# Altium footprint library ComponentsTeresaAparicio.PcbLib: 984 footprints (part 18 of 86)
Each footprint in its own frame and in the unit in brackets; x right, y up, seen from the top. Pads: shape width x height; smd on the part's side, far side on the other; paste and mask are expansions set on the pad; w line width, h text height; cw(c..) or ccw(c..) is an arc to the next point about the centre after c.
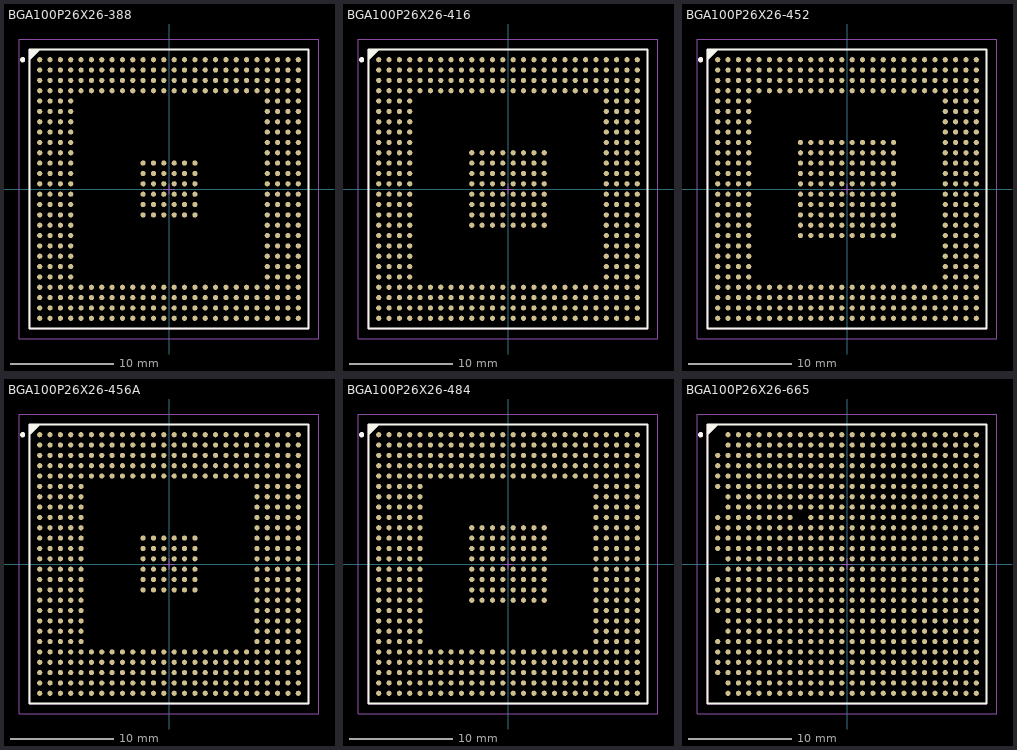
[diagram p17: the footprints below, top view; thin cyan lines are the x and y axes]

## BGA100P26X26-388 [mm] "BGA, 388-Leads, Body 27x27mm, Pitch 1mm"
height 2.55
pads (388):
  round 0.5 smd: A1(-12.5,12.5) A2(-11.5,12.5) A3(-10.5,12.5) A4(-9.5,12.5) A5(-8.5,12.5) A6(-7.5,12.5) A7(-6.5,12.5) A8(-5.5,12.5) A9(-4.5,12.5) A10(-3.5,12.5) A11(-2.5,12.5) A12(-1.5,12.5) A13(-0.5,12.5) A14(0.5,12.5) A15(1.5,12.5) A16(2.5,12.5) A17(3.5,12.5) A18(4.5,12.5) A19(5.5,12.5) A20(6.5,12.5) A21(7.5,12.5) A22(8.5,12.5) A23(9.5,12.5) A24(10.5,12.5) A25(11.5,12.5) A26(12.5,12.5) AA1(-12.5,-7.5) AA2(-11.5,-7.5) AA3(-10.5,-7.5) AA4(-9.5,-7.5) AA23(9.5,-7.5) AA24(10.5,-7.5) AA25(11.5,-7.5) AA26(12.5,-7.5) AB1(-12.5,-8.5) AB2(-11.5,-8.5) AB3(-10.5,-8.5) AB4(-9.5,-8.5) AB23(9.5,-8.5) AB24(10.5,-8.5) AB25(11.5,-8.5) AB26(12.5,-8.5) AC1(-12.5,-9.5) AC2(-11.5,-9.5) AC3(-10.5,-9.5) AC4(-9.5,-9.5) AC5(-8.5,-9.5) AC6(-7.5,-9.5) AC7(-6.5,-9.5) AC8(-5.5,-9.5) AC9(-4.5,-9.5) AC10(-3.5,-9.5) AC11(-2.5,-9.5) AC12(-1.5,-9.5) AC13(-0.5,-9.5) AC14(0.5,-9.5) AC15(1.5,-9.5) AC16(2.5,-9.5) AC17(3.5,-9.5) AC18(4.5,-9.5) AC19(5.5,-9.5) AC20(6.5,-9.5) AC21(7.5,-9.5) AC22(8.5,-9.5) AC23(9.5,-9.5) AC24(10.5,-9.5) AC25(11.5,-9.5) AC26(12.5,-9.5) AD1(-12.5,-10.5) AD2(-11.5,-10.5) AD3(-10.5,-10.5) AD4(-9.5,-10.5) AD5(-8.5,-10.5) AD6(-7.5,-10.5) AD7(-6.5,-10.5) AD8(-5.5,-10.5) AD9(-4.5,-10.5) AD10(-3.5,-10.5) AD11(-2.5,-10.5) AD12(-1.5,-10.5) AD13(-0.5,-10.5) AD14(0.5,-10.5) AD15(1.5,-10.5) AD16(2.5,-10.5) AD17(3.5,-10.5) AD18(4.5,-10.5) AD19(5.5,-10.5) AD20(6.5,-10.5) AD21(7.5,-10.5) AD22(8.5,-10.5) AD23(9.5,-10.5) AD24(10.5,-10.5) AD25(11.5,-10.5) AD26(12.5,-10.5) AE1(-12.5,-11.5) AE2(-11.5,-11.5) AE3(-10.5,-11.5) AE4(-9.5,-11.5) AE5(-8.5,-11.5) AE6(-7.5,-11.5) AE7(-6.5,-11.5) AE8(-5.5,-11.5) AE9(-4.5,-11.5) AE10(-3.5,-11.5) AE11(-2.5,-11.5) AE12(-1.5,-11.5) AE13(-0.5,-11.5) AE14(0.5,-11.5) AE15(1.5,-11.5) AE16(2.5,-11.5) AE17(3.5,-11.5) AE18(4.5,-11.5) AE19(5.5,-11.5) AE20(6.5,-11.5) AE21(7.5,-11.5) AE22(8.5,-11.5) AE23(9.5,-11.5) AE24(10.5,-11.5) AE25(11.5,-11.5) AE26(12.5,-11.5) AF1(-12.5,-12.5) AF2(-11.5,-12.5) AF3(-10.5,-12.5) AF4(-9.5,-12.5) AF5(-8.5,-12.5) AF6(-7.5,-12.5) AF7(-6.5,-12.5) AF8(-5.5,-12.5) AF9(-4.5,-12.5) AF10(-3.5,-12.5) AF11(-2.5,-12.5) AF12(-1.5,-12.5) AF13(-0.5,-12.5) AF14(0.5,-12.5) AF15(1.5,-12.5) AF16(2.5,-12.5) AF17(3.5,-12.5) AF18(4.5,-12.5) AF19(5.5,-12.5) AF20(6.5,-12.5) AF21(7.5,-12.5) AF22(8.5,-12.5) AF23(9.5,-12.5) AF24(10.5,-12.5) AF25(11.5,-12.5) AF26(12.5,-12.5) B1(-12.5,11.5) B2(-11.5,11.5) B3(-10.5,11.5) B4(-9.5,11.5) B5(-8.5,11.5) B6(-7.5,11.5) B7(-6.5,11.5) B8(-5.5,11.5) B9(-4.5,11.5) B10(-3.5,11.5) B11(-2.5,11.5) B12(-1.5,11.5) B13(-0.5,11.5) B14(0.5,11.5) B15(1.5,11.5) B16(2.5,11.5) B17(3.5,11.5) B18(4.5,11.5) B19(5.5,11.5) B20(6.5,11.5) B21(7.5,11.5) B22(8.5,11.5) B23(9.5,11.5) B24(10.5,11.5) B25(11.5,11.5) B26(12.5,11.5) C1(-12.5,10.5) C2(-11.5,10.5) C3(-10.5,10.5) C4(-9.5,10.5) C5(-8.5,10.5) C6(-7.5,10.5) C7(-6.5,10.5) C8(-5.5,10.5) C9(-4.5,10.5) C10(-3.5,10.5) C11(-2.5,10.5) C12(-1.5,10.5) C13(-0.5,10.5) C14(0.5,10.5) C15(1.5,10.5) C16(2.5,10.5) C17(3.5,10.5) C18(4.5,10.5) C19(5.5,10.5) C20(6.5,10.5) C21(7.5,10.5) C22(8.5,10.5) C23(9.5,10.5) C24(10.5,10.5) C25(11.5,10.5) C26(12.5,10.5) D1(-12.5,9.5) D2(-11.5,9.5) D3(-10.5,9.5) D4(-9.5,9.5) D5(-8.5,9.5) D6(-7.5,9.5) D7(-6.5,9.5) D8(-5.5,9.5) D9(-4.5,9.5) D10(-3.5,9.5) D11(-2.5,9.5) D12(-1.5,9.5) D13(-0.5,9.5) D14(0.5,9.5) D15(1.5,9.5) D16(2.5,9.5) D17(3.5,9.5) D18(4.5,9.5) D19(5.5,9.5) D20(6.5,9.5) D21(7.5,9.5) D22(8.5,9.5) D23(9.5,9.5) D24(10.5,9.5) D25(11.5,9.5) D26(12.5,9.5) E1(-12.5,8.5) E2(-11.5,8.5) E3(-10.5,8.5) E4(-9.5,8.5) E23(9.5,8.5) E24(10.5,8.5) E25(11.5,8.5) E26(12.5,8.5) F1(-12.5,7.5) F2(-11.5,7.5) F3(-10.5,7.5) F4(-9.5,7.5) F23(9.5,7.5) F24(10.5,7.5) F25(11.5,7.5) F26(12.5,7.5) G1(-12.5,6.5) G2(-11.5,6.5) G3(-10.5,6.5) G4(-9.5,6.5) G23(9.5,6.5) G24(10.5,6.5) G25(11.5,6.5) G26(12.5,6.5) H1(-12.5,5.5) H2(-11.5,5.5) H3(-10.5,5.5) H4(-9.5,5.5) H23(9.5,5.5) H24(10.5,5.5) H25(11.5,5.5) H26(12.5,5.5) J1(-12.5,4.5) J2(-11.5,4.5) J3(-10.5,4.5) J4(-9.5,4.5) J23(9.5,4.5) J24(10.5,4.5) J25(11.5,4.5) J26(12.5,4.5) K1(-12.5,3.5) K2(-11.5,3.5) K3(-10.5,3.5) K4(-9.5,3.5) K23(9.5,3.5) K24(10.5,3.5) K25(11.5,3.5) K26(12.5,3.5) L1(-12.5,2.5) L2(-11.5,2.5) L3(-10.5,2.5) L4(-9.5,2.5) L11(-2.5,2.5) L12(-1.5,2.5) L13(-0.5,2.5) L14(0.5,2.5) L15(1.5,2.5) L16(2.5,2.5) L23(9.5,2.5) L24(10.5,2.5) L25(11.5,2.5) L26(12.5,2.5) M1(-12.5,1.5) M2(-11.5,1.5) M3(-10.5,1.5) M4(-9.5,1.5) M11(-2.5,1.5) M12(-1.5,1.5) M13(-0.5,1.5) M14(0.5,1.5) M15(1.5,1.5) M16(2.5,1.5) M23(9.5,1.5) M24(10.5,1.5) M25(11.5,1.5) M26(12.5,1.5) N1(-12.5,0.5) N2(-11.5,0.5) N3(-10.5,0.5) N4(-9.5,0.5) N11(-2.5,0.5) N12(-1.5,0.5) N13(-0.5,0.5) N14(0.5,0.5) N15(1.5,0.5) N16(2.5,0.5) N23(9.5,0.5) N24(10.5,0.5) N25(11.5,0.5) N26(12.5,0.5) P1(-12.5,-0.5) P2(-11.5,-0.5) P3(-10.5,-0.5) P4(-9.5,-0.5) P11(-2.5,-0.5) P12(-1.5,-0.5) P13(-0.5,-0.5) P14(0.5,-0.5) P15(1.5,-0.5) P16(2.5,-0.5) P23(9.5,-0.5) P24(10.5,-0.5) P25(11.5,-0.5) P26(12.5,-0.5) R1(-12.5,-1.5) R2(-11.5,-1.5) R3(-10.5,-1.5) R4(-9.5,-1.5) R11(-2.5,-1.5) R12(-1.5,-1.5) R13(-0.5,-1.5) R14(0.5,-1.5) R15(1.5,-1.5) R16(2.5,-1.5) R23(9.5,-1.5) R24(10.5,-1.5) R25(11.5,-1.5) R26(12.5,-1.5) T1(-12.5,-2.5) T2(-11.5,-2.5) T3(-10.5,-2.5) T4(-9.5,-2.5) T11(-2.5,-2.5) T12(-1.5,-2.5) T13(-0.5,-2.5) T14(0.5,-2.5) T15(1.5,-2.5) T16(2.5,-2.5) T23(9.5,-2.5) T24(10.5,-2.5) T25(11.5,-2.5) T26(12.5,-2.5) U1(-12.5,-3.5) U2(-11.5,-3.5) U3(-10.5,-3.5) U4(-9.5,-3.5) U23(9.5,-3.5) U24(10.5,-3.5) U25(11.5,-3.5) U26(12.5,-3.5) V1(-12.5,-4.5) V2(-11.5,-4.5) V3(-10.5,-4.5) V4(-9.5,-4.5) V23(9.5,-4.5) V24(10.5,-4.5) V25(11.5,-4.5) V26(12.5,-4.5) W1(-12.5,-5.5) W2(-11.5,-5.5) W3(-10.5,-5.5) W4(-9.5,-5.5) W23(9.5,-5.5) W24(10.5,-5.5) W25(11.5,-5.5) W26(12.5,-5.5) Y1(-12.5,-6.5) Y2(-11.5,-6.5) Y3(-10.5,-6.5) Y4(-9.5,-6.5) Y23(9.5,-6.5) Y24(10.5,-6.5) Y25(11.5,-6.5) Y26(12.5,-6.5)
Top Overlay:
  circle w0.25: c-14.15,12.5 r0.125
  region: -12.5,13.5 -13.5,12.5 -13.5,13.5
  lines w0.2: -13.5,12.5 -12.5,13.5 ; -13.5,-13.5 -13.5,13.5 13.5,13.5 13.5,-13.5 -13.5,-13.5
Mechanical 13:
  lines w0.1: -13.5,-13.5 -13.5,13.5 13.5,13.5 13.5,-13.5 -13.5,-13.5
Mechanical 15:
  lines w0.1: -0.5,0 0.5,0 ; 0,-0.5 0,0.5 ; -14.5,-14.5 -14.5,14.5 14.5,14.5 14.5,-14.5 -14.5,-14.5
3D body: height 0, standoff 0, extent -13.5,-13.5 13.5,13.5

## BGA100P26X26-416 [mm] "BGA, 416-Leads, Body 27x27mm, Pitch 1mm"
height 2.6
pads (416):
  round 0.5 smd: A1(-12.5,12.5) A2(-11.5,12.5) A3(-10.5,12.5) A4(-9.5,12.5) A5(-8.5,12.5) A6(-7.5,12.5) A7(-6.5,12.5) A8(-5.5,12.5) A9(-4.5,12.5) A10(-3.5,12.5) A11(-2.5,12.5) A12(-1.5,12.5) A13(-0.5,12.5) A14(0.5,12.5) A15(1.5,12.5) A16(2.5,12.5) A17(3.5,12.5) A18(4.5,12.5) A19(5.5,12.5) A20(6.5,12.5) A21(7.5,12.5) A22(8.5,12.5) A23(9.5,12.5) A24(10.5,12.5) A25(11.5,12.5) A26(12.5,12.5) AA1(-12.5,-7.5) AA2(-11.5,-7.5) AA3(-10.5,-7.5) AA4(-9.5,-7.5) AA23(9.5,-7.5) AA24(10.5,-7.5) AA25(11.5,-7.5) AA26(12.5,-7.5) AB1(-12.5,-8.5) AB2(-11.5,-8.5) AB3(-10.5,-8.5) AB4(-9.5,-8.5) AB23(9.5,-8.5) AB24(10.5,-8.5) AB25(11.5,-8.5) AB26(12.5,-8.5) AC1(-12.5,-9.5) AC2(-11.5,-9.5) AC3(-10.5,-9.5) AC4(-9.5,-9.5) AC5(-8.5,-9.5) AC6(-7.5,-9.5) AC7(-6.5,-9.5) AC8(-5.5,-9.5) AC9(-4.5,-9.5) AC10(-3.5,-9.5) AC11(-2.5,-9.5) AC12(-1.5,-9.5) AC13(-0.5,-9.5) AC14(0.5,-9.5) AC15(1.5,-9.5) AC16(2.5,-9.5) AC17(3.5,-9.5) AC18(4.5,-9.5) AC19(5.5,-9.5) AC20(6.5,-9.5) AC21(7.5,-9.5) AC22(8.5,-9.5) AC23(9.5,-9.5) AC24(10.5,-9.5) AC25(11.5,-9.5) AC26(12.5,-9.5) AD1(-12.5,-10.5) AD2(-11.5,-10.5) AD3(-10.5,-10.5) AD4(-9.5,-10.5) AD5(-8.5,-10.5) AD6(-7.5,-10.5) AD7(-6.5,-10.5) AD8(-5.5,-10.5) AD9(-4.5,-10.5) AD10(-3.5,-10.5) AD11(-2.5,-10.5) AD12(-1.5,-10.5) AD13(-0.5,-10.5) AD14(0.5,-10.5) AD15(1.5,-10.5) AD16(2.5,-10.5) AD17(3.5,-10.5) AD18(4.5,-10.5) AD19(5.5,-10.5) AD20(6.5,-10.5) AD21(7.5,-10.5) AD22(8.5,-10.5) AD23(9.5,-10.5) AD24(10.5,-10.5) AD25(11.5,-10.5) AD26(12.5,-10.5) AE1(-12.5,-11.5) AE2(-11.5,-11.5) AE3(-10.5,-11.5) AE4(-9.5,-11.5) AE5(-8.5,-11.5) AE6(-7.5,-11.5) AE7(-6.5,-11.5) AE8(-5.5,-11.5) AE9(-4.5,-11.5) AE10(-3.5,-11.5) AE11(-2.5,-11.5) AE12(-1.5,-11.5) AE13(-0.5,-11.5) AE14(0.5,-11.5) AE15(1.5,-11.5) AE16(2.5,-11.5) AE17(3.5,-11.5) AE18(4.5,-11.5) AE19(5.5,-11.5) AE20(6.5,-11.5) AE21(7.5,-11.5) AE22(8.5,-11.5) AE23(9.5,-11.5) AE24(10.5,-11.5) AE25(11.5,-11.5) AE26(12.5,-11.5) AF1(-12.5,-12.5) AF2(-11.5,-12.5) AF3(-10.5,-12.5) AF4(-9.5,-12.5) AF5(-8.5,-12.5) AF6(-7.5,-12.5) AF7(-6.5,-12.5) AF8(-5.5,-12.5) AF9(-4.5,-12.5) AF10(-3.5,-12.5) AF11(-2.5,-12.5) AF12(-1.5,-12.5) AF13(-0.5,-12.5) AF14(0.5,-12.5) AF15(1.5,-12.5) AF16(2.5,-12.5) AF17(3.5,-12.5) AF18(4.5,-12.5) AF19(5.5,-12.5) AF20(6.5,-12.5) AF21(7.5,-12.5) AF22(8.5,-12.5) AF23(9.5,-12.5) AF24(10.5,-12.5) AF25(11.5,-12.5) AF26(12.5,-12.5) B1(-12.5,11.5) B2(-11.5,11.5) B3(-10.5,11.5) B4(-9.5,11.5) B5(-8.5,11.5) B6(-7.5,11.5) B7(-6.5,11.5) B8(-5.5,11.5) B9(-4.5,11.5) B10(-3.5,11.5) B11(-2.5,11.5) B12(-1.5,11.5) B13(-0.5,11.5) B14(0.5,11.5) B15(1.5,11.5) B16(2.5,11.5) B17(3.5,11.5) B18(4.5,11.5) B19(5.5,11.5) B20(6.5,11.5) B21(7.5,11.5) B22(8.5,11.5) B23(9.5,11.5) B24(10.5,11.5) B25(11.5,11.5) B26(12.5,11.5) C1(-12.5,10.5) C2(-11.5,10.5) C3(-10.5,10.5) C4(-9.5,10.5) C5(-8.5,10.5) C6(-7.5,10.5) C7(-6.5,10.5) C8(-5.5,10.5) C9(-4.5,10.5) C10(-3.5,10.5) C11(-2.5,10.5) C12(-1.5,10.5) C13(-0.5,10.5) C14(0.5,10.5) C15(1.5,10.5) C16(2.5,10.5) C17(3.5,10.5) C18(4.5,10.5) C19(5.5,10.5) C20(6.5,10.5) C21(7.5,10.5) C22(8.5,10.5) C23(9.5,10.5) C24(10.5,10.5) C25(11.5,10.5) C26(12.5,10.5) D1(-12.5,9.5) D2(-11.5,9.5) D3(-10.5,9.5) D4(-9.5,9.5) D5(-8.5,9.5) D6(-7.5,9.5) D7(-6.5,9.5) D8(-5.5,9.5) D9(-4.5,9.5) D10(-3.5,9.5) D11(-2.5,9.5) D12(-1.5,9.5) D13(-0.5,9.5) D14(0.5,9.5) D15(1.5,9.5) D16(2.5,9.5) D17(3.5,9.5) D18(4.5,9.5) D19(5.5,9.5) D20(6.5,9.5) D21(7.5,9.5) D22(8.5,9.5) D23(9.5,9.5) D24(10.5,9.5) D25(11.5,9.5) D26(12.5,9.5) E1(-12.5,8.5) E2(-11.5,8.5) E3(-10.5,8.5) E4(-9.5,8.5) E23(9.5,8.5) E24(10.5,8.5) E25(11.5,8.5) E26(12.5,8.5) F1(-12.5,7.5) F2(-11.5,7.5) F3(-10.5,7.5) F4(-9.5,7.5) F23(9.5,7.5) F24(10.5,7.5) F25(11.5,7.5) F26(12.5,7.5) G1(-12.5,6.5) G2(-11.5,6.5) G3(-10.5,6.5) G4(-9.5,6.5) G23(9.5,6.5) G24(10.5,6.5) G25(11.5,6.5) G26(12.5,6.5) H1(-12.5,5.5) H2(-11.5,5.5) H3(-10.5,5.5) H4(-9.5,5.5) H23(9.5,5.5) H24(10.5,5.5) H25(11.5,5.5) H26(12.5,5.5) J1(-12.5,4.5) J2(-11.5,4.5) J3(-10.5,4.5) J4(-9.5,4.5) J23(9.5,4.5) J24(10.5,4.5) J25(11.5,4.5) J26(12.5,4.5) K1(-12.5,3.5) K2(-11.5,3.5) K3(-10.5,3.5) K4(-9.5,3.5) K10(-3.5,3.5) K11(-2.5,3.5) K12(-1.5,3.5) K13(-0.5,3.5) K14(0.5,3.5) K15(1.5,3.5) K16(2.5,3.5) K17(3.5,3.5) K23(9.5,3.5) K24(10.5,3.5) K25(11.5,3.5) K26(12.5,3.5) L1(-12.5,2.5) L2(-11.5,2.5) L3(-10.5,2.5) L4(-9.5,2.5) L10(-3.5,2.5) L11(-2.5,2.5) L12(-1.5,2.5) L13(-0.5,2.5) L14(0.5,2.5) L15(1.5,2.5) L16(2.5,2.5) L17(3.5,2.5) L23(9.5,2.5) L24(10.5,2.5) L25(11.5,2.5) L26(12.5,2.5) M1(-12.5,1.5) M2(-11.5,1.5) M3(-10.5,1.5) M4(-9.5,1.5) M10(-3.5,1.5) M11(-2.5,1.5) M12(-1.5,1.5) M13(-0.5,1.5) M14(0.5,1.5) M15(1.5,1.5) M16(2.5,1.5) M17(3.5,1.5) M23(9.5,1.5) M24(10.5,1.5) M25(11.5,1.5) M26(12.5,1.5) N1(-12.5,0.5) N2(-11.5,0.5) N3(-10.5,0.5) N4(-9.5,0.5) N10(-3.5,0.5) N11(-2.5,0.5) N12(-1.5,0.5) N13(-0.5,0.5) N14(0.5,0.5) N15(1.5,0.5) N16(2.5,0.5) N17(3.5,0.5) N23(9.5,0.5) N24(10.5,0.5) N25(11.5,0.5) N26(12.5,0.5) P1(-12.5,-0.5) P2(-11.5,-0.5) P3(-10.5,-0.5) P4(-9.5,-0.5) P10(-3.5,-0.5) P11(-2.5,-0.5) P12(-1.5,-0.5) P13(-0.5,-0.5) P14(0.5,-0.5) P15(1.5,-0.5) P16(2.5,-0.5) P17(3.5,-0.5) P23(9.5,-0.5) P24(10.5,-0.5) P25(11.5,-0.5) P26(12.5,-0.5) R1(-12.5,-1.5) R2(-11.5,-1.5) R3(-10.5,-1.5) R4(-9.5,-1.5) R10(-3.5,-1.5) R11(-2.5,-1.5) R12(-1.5,-1.5) R13(-0.5,-1.5) R14(0.5,-1.5) R15(1.5,-1.5) R16(2.5,-1.5) R17(3.5,-1.5) R23(9.5,-1.5) R24(10.5,-1.5) R25(11.5,-1.5) R26(12.5,-1.5) T1(-12.5,-2.5) T2(-11.5,-2.5) T3(-10.5,-2.5) T4(-9.5,-2.5) T10(-3.5,-2.5) T11(-2.5,-2.5) T12(-1.5,-2.5) T13(-0.5,-2.5) T14(0.5,-2.5) T15(1.5,-2.5) T16(2.5,-2.5) T17(3.5,-2.5) T23(9.5,-2.5) T24(10.5,-2.5) T25(11.5,-2.5) T26(12.5,-2.5) U1(-12.5,-3.5) U2(-11.5,-3.5) U3(-10.5,-3.5) U4(-9.5,-3.5) U10(-3.5,-3.5) U11(-2.5,-3.5) U12(-1.5,-3.5) U13(-0.5,-3.5) U14(0.5,-3.5) U15(1.5,-3.5) U16(2.5,-3.5) U17(3.5,-3.5) U23(9.5,-3.5) U24(10.5,-3.5) U25(11.5,-3.5) U26(12.5,-3.5) V1(-12.5,-4.5) V2(-11.5,-4.5) V3(-10.5,-4.5) V4(-9.5,-4.5) V23(9.5,-4.5) V24(10.5,-4.5) V25(11.5,-4.5) V26(12.5,-4.5) W1(-12.5,-5.5) W2(-11.5,-5.5) W3(-10.5,-5.5) W4(-9.5,-5.5) W23(9.5,-5.5) W24(10.5,-5.5) W25(11.5,-5.5) W26(12.5,-5.5) Y1(-12.5,-6.5) Y2(-11.5,-6.5) Y3(-10.5,-6.5) Y4(-9.5,-6.5) Y23(9.5,-6.5) Y24(10.5,-6.5) Y25(11.5,-6.5) Y26(12.5,-6.5)
Top Overlay:
  circle w0.25: c-14.15,12.5 r0.125
  region: -12.5,13.5 -13.5,12.5 -13.5,13.5
  lines w0.2: -13.5,12.5 -12.5,13.5 ; -13.5,-13.5 13.5,-13.5 13.5,13.5 -13.5,13.5 -13.5,-13.5
Mechanical 13:
  lines w0.1: -13.5,-13.5 13.5,-13.5 13.5,13.5 -13.5,13.5 -13.5,-13.5
Mechanical 15:
  lines w0.1: -0.5,0 0.5,0 ; 0,-0.5 0,0.5 ; -14.5,-14.5 14.5,-14.5 14.5,14.5 -14.5,14.5 -14.5,-14.5
3D body: height 0, standoff 0, extent -13.5,-13.5 13.5,13.5

## BGA100P26X26-452 [mm] "452-Ball Ball Grid Array 1 mm Pitch"
height 3.5
pads (452):
  round 0.5 smd: A1(-12.5,12.5) A2(-11.5,12.5) A3(-10.5,12.5) A4(-9.5,12.5) A5(-8.5,12.5) A6(-7.5,12.5) A7(-6.5,12.5) A8(-5.5,12.5) A9(-4.5,12.5) A10(-3.5,12.5) A11(-2.5,12.5) A12(-1.5,12.5) A13(-0.5,12.5) A14(0.5,12.5) A15(1.5,12.5) A16(2.5,12.5) A17(3.5,12.5) A18(4.5,12.5) A19(5.5,12.5) A20(6.5,12.5) A21(7.5,12.5) A22(8.5,12.5) A23(9.5,12.5) A24(10.5,12.5) A25(11.5,12.5) A26(12.5,12.5) AA1(-12.5,-7.5) AA2(-11.5,-7.5) AA3(-10.5,-7.5) AA4(-9.5,-7.5) AA23(9.5,-7.5) AA24(10.5,-7.5) AA25(11.5,-7.5) AA26(12.5,-7.5) AB1(-12.5,-8.5) AB2(-11.5,-8.5) AB3(-10.5,-8.5) AB4(-9.5,-8.5) AB23(9.5,-8.5) AB24(10.5,-8.5) AB25(11.5,-8.5) AB26(12.5,-8.5) AC1(-12.5,-9.5) AC2(-11.5,-9.5) AC3(-10.5,-9.5) AC4(-9.5,-9.5) AC5(-8.5,-9.5) AC6(-7.5,-9.5) AC7(-6.5,-9.5) AC8(-5.5,-9.5) AC9(-4.5,-9.5) AC10(-3.5,-9.5) AC11(-2.5,-9.5) AC12(-1.5,-9.5) AC13(-0.5,-9.5) AC14(0.5,-9.5) AC15(1.5,-9.5) AC16(2.5,-9.5) AC17(3.5,-9.5) AC18(4.5,-9.5) AC19(5.5,-9.5) AC20(6.5,-9.5) AC21(7.5,-9.5) AC22(8.5,-9.5) AC23(9.5,-9.5) AC24(10.5,-9.5) AC25(11.5,-9.5) AC26(12.5,-9.5) AD1(-12.5,-10.5) AD2(-11.5,-10.5) AD3(-10.5,-10.5) AD4(-9.5,-10.5) AD5(-8.5,-10.5) AD6(-7.5,-10.5) AD7(-6.5,-10.5) AD8(-5.5,-10.5) AD9(-4.5,-10.5) AD10(-3.5,-10.5) AD11(-2.5,-10.5) AD12(-1.5,-10.5) AD13(-0.5,-10.5) AD14(0.5,-10.5) AD15(1.5,-10.5) AD16(2.5,-10.5) AD17(3.5,-10.5) AD18(4.5,-10.5) AD19(5.5,-10.5) AD20(6.5,-10.5) AD21(7.5,-10.5) AD22(8.5,-10.5) AD23(9.5,-10.5) AD24(10.5,-10.5) AD25(11.5,-10.5) AD26(12.5,-10.5) AE1(-12.5,-11.5) AE2(-11.5,-11.5) AE3(-10.5,-11.5) AE4(-9.5,-11.5) AE5(-8.5,-11.5) AE6(-7.5,-11.5) AE7(-6.5,-11.5) AE8(-5.5,-11.5) AE9(-4.5,-11.5) AE10(-3.5,-11.5) AE11(-2.5,-11.5) AE12(-1.5,-11.5) AE13(-0.5,-11.5) AE14(0.5,-11.5) AE15(1.5,-11.5) AE16(2.5,-11.5) AE17(3.5,-11.5) AE18(4.5,-11.5) AE19(5.5,-11.5) AE20(6.5,-11.5) AE21(7.5,-11.5) AE22(8.5,-11.5) AE23(9.5,-11.5) AE24(10.5,-11.5) AE25(11.5,-11.5) AE26(12.5,-11.5) AF1(-12.5,-12.5) AF2(-11.5,-12.5) AF3(-10.5,-12.5) AF4(-9.5,-12.5) AF5(-8.5,-12.5) AF6(-7.5,-12.5) AF7(-6.5,-12.5) AF8(-5.5,-12.5) AF9(-4.5,-12.5) AF10(-3.5,-12.5) AF11(-2.5,-12.5) AF12(-1.5,-12.5) AF13(-0.5,-12.5) AF14(0.5,-12.5) AF15(1.5,-12.5) AF16(2.5,-12.5) AF17(3.5,-12.5) AF18(4.5,-12.5) AF19(5.5,-12.5) AF20(6.5,-12.5) AF21(7.5,-12.5) AF22(8.5,-12.5) AF23(9.5,-12.5) AF24(10.5,-12.5) AF25(11.5,-12.5) AF26(12.5,-12.5) B1(-12.5,11.5) B2(-11.5,11.5) B3(-10.5,11.5) B4(-9.5,11.5) B5(-8.5,11.5) B6(-7.5,11.5) B7(-6.5,11.5) B8(-5.5,11.5) B9(-4.5,11.5) B10(-3.5,11.5) B11(-2.5,11.5) B12(-1.5,11.5) B13(-0.5,11.5) B14(0.5,11.5) B15(1.5,11.5) B16(2.5,11.5) B17(3.5,11.5) B18(4.5,11.5) B19(5.5,11.5) B20(6.5,11.5) B21(7.5,11.5) B22(8.5,11.5) B23(9.5,11.5) B24(10.5,11.5) B25(11.5,11.5) B26(12.5,11.5) C1(-12.5,10.5) C2(-11.5,10.5) C3(-10.5,10.5) C4(-9.5,10.5) C5(-8.5,10.5) C6(-7.5,10.5) C7(-6.5,10.5) C8(-5.5,10.5) C9(-4.5,10.5) C10(-3.5,10.5) C11(-2.5,10.5) C12(-1.5,10.5) C13(-0.5,10.5) C14(0.5,10.5) C15(1.5,10.5) C16(2.5,10.5) C17(3.5,10.5) C18(4.5,10.5) C19(5.5,10.5) C20(6.5,10.5) C21(7.5,10.5) C22(8.5,10.5) C23(9.5,10.5) C24(10.5,10.5) C25(11.5,10.5) C26(12.5,10.5) D1(-12.5,9.5) D2(-11.5,9.5) D3(-10.5,9.5) D4(-9.5,9.5) D5(-8.5,9.5) D6(-7.5,9.5) D7(-6.5,9.5) D8(-5.5,9.5) D9(-4.5,9.5) D10(-3.5,9.5) D11(-2.5,9.5) D12(-1.5,9.5) D13(-0.5,9.5) D14(0.5,9.5) D15(1.5,9.5) D16(2.5,9.5) D17(3.5,9.5) D18(4.5,9.5) D19(5.5,9.5) D20(6.5,9.5) D21(7.5,9.5) D22(8.5,9.5) D23(9.5,9.5) D24(10.5,9.5) D25(11.5,9.5) D26(12.5,9.5) E1(-12.5,8.5) E2(-11.5,8.5) E3(-10.5,8.5) E4(-9.5,8.5) E23(9.5,8.5) E24(10.5,8.5) E25(11.5,8.5) E26(12.5,8.5) F1(-12.5,7.5) F2(-11.5,7.5) F3(-10.5,7.5) F4(-9.5,7.5) F23(9.5,7.5) F24(10.5,7.5) F25(11.5,7.5) F26(12.5,7.5) G1(-12.5,6.5) G2(-11.5,6.5) G3(-10.5,6.5) G4(-9.5,6.5) G23(9.5,6.5) G24(10.5,6.5) G25(11.5,6.5) G26(12.5,6.5) H1(-12.5,5.5) H2(-11.5,5.5) H3(-10.5,5.5) H4(-9.5,5.5) H23(9.5,5.5) H24(10.5,5.5) H25(11.5,5.5) H26(12.5,5.5) J1(-12.5,4.5) J2(-11.5,4.5) J3(-10.5,4.5) J4(-9.5,4.5) J9(-4.5,4.5) J10(-3.5,4.5) J11(-2.5,4.5) J12(-1.5,4.5) J13(-0.5,4.5) J14(0.5,4.5) J15(1.5,4.5) J16(2.5,4.5) J17(3.5,4.5) J18(4.5,4.5) J23(9.5,4.5) J24(10.5,4.5) J25(11.5,4.5) J26(12.5,4.5) K1(-12.5,3.5) K2(-11.5,3.5) K3(-10.5,3.5) K4(-9.5,3.5) K9(-4.5,3.5) K10(-3.5,3.5) K11(-2.5,3.5) K12(-1.5,3.5) K13(-0.5,3.5) K14(0.5,3.5) K15(1.5,3.5) K16(2.5,3.5) K17(3.5,3.5) K18(4.5,3.5) K23(9.5,3.5) K24(10.5,3.5) K25(11.5,3.5) K26(12.5,3.5) L1(-12.5,2.5) L2(-11.5,2.5) L3(-10.5,2.5) L4(-9.5,2.5) L9(-4.5,2.5) L10(-3.5,2.5) L11(-2.5,2.5) L12(-1.5,2.5) L13(-0.5,2.5) L14(0.5,2.5) L15(1.5,2.5) L16(2.5,2.5) L17(3.5,2.5) L18(4.5,2.5) L23(9.5,2.5) L24(10.5,2.5) L25(11.5,2.5) L26(12.5,2.5) M1(-12.5,1.5) M2(-11.5,1.5) M3(-10.5,1.5) M4(-9.5,1.5) M9(-4.5,1.5) M10(-3.5,1.5) M11(-2.5,1.5) M12(-1.5,1.5) M13(-0.5,1.5) M14(0.5,1.5) M15(1.5,1.5) M16(2.5,1.5) M17(3.5,1.5) M18(4.5,1.5) M23(9.5,1.5) M24(10.5,1.5) M25(11.5,1.5) M26(12.5,1.5) N1(-12.5,0.5) N2(-11.5,0.5) N3(-10.5,0.5) N4(-9.5,0.5) N9(-4.5,0.5) N10(-3.5,0.5) N11(-2.5,0.5) N12(-1.5,0.5) N13(-0.5,0.5) N14(0.5,0.5) N15(1.5,0.5) N16(2.5,0.5) N17(3.5,0.5) N18(4.5,0.5) N23(9.5,0.5) N24(10.5,0.5) N25(11.5,0.5) N26(12.5,0.5) P1(-12.5,-0.5) P2(-11.5,-0.5) P3(-10.5,-0.5) P4(-9.5,-0.5) P9(-4.5,-0.5) P10(-3.5,-0.5) P11(-2.5,-0.5) P12(-1.5,-0.5) P13(-0.5,-0.5) P14(0.5,-0.5) P15(1.5,-0.5) P16(2.5,-0.5) P17(3.5,-0.5) P18(4.5,-0.5) P23(9.5,-0.5) P24(10.5,-0.5) P25(11.5,-0.5) P26(12.5,-0.5) R1(-12.5,-1.5) R2(-11.5,-1.5) R3(-10.5,-1.5) R4(-9.5,-1.5) R9(-4.5,-1.5) R10(-3.5,-1.5) R11(-2.5,-1.5) R12(-1.5,-1.5) R13(-0.5,-1.5) R14(0.5,-1.5) R15(1.5,-1.5) R16(2.5,-1.5) R17(3.5,-1.5) R18(4.5,-1.5) R23(9.5,-1.5) R24(10.5,-1.5) R25(11.5,-1.5) R26(12.5,-1.5) T1(-12.5,-2.5) T2(-11.5,-2.5) T3(-10.5,-2.5) T4(-9.5,-2.5) T9(-4.5,-2.5) T10(-3.5,-2.5) T11(-2.5,-2.5) T12(-1.5,-2.5) T13(-0.5,-2.5) T14(0.5,-2.5) T15(1.5,-2.5) T16(2.5,-2.5) T17(3.5,-2.5) T18(4.5,-2.5) T23(9.5,-2.5) T24(10.5,-2.5) T25(11.5,-2.5) T26(12.5,-2.5) U1(-12.5,-3.5) U2(-11.5,-3.5) U3(-10.5,-3.5) U4(-9.5,-3.5) U9(-4.5,-3.5) U10(-3.5,-3.5) U11(-2.5,-3.5) U12(-1.5,-3.5) U13(-0.5,-3.5) U14(0.5,-3.5) U15(1.5,-3.5) U16(2.5,-3.5) U17(3.5,-3.5) U18(4.5,-3.5) U23(9.5,-3.5) U24(10.5,-3.5) U25(11.5,-3.5) U26(12.5,-3.5) V1(-12.5,-4.5) V2(-11.5,-4.5) V3(-10.5,-4.5) V4(-9.5,-4.5) V9(-4.5,-4.5) V10(-3.5,-4.5) V11(-2.5,-4.5) V12(-1.5,-4.5) V13(-0.5,-4.5) V14(0.5,-4.5) V15(1.5,-4.5) V16(2.5,-4.5) V17(3.5,-4.5) V18(4.5,-4.5) V23(9.5,-4.5) V24(10.5,-4.5) V25(11.5,-4.5) V26(12.5,-4.5) W1(-12.5,-5.5) W2(-11.5,-5.5) W3(-10.5,-5.5) W4(-9.5,-5.5) W23(9.5,-5.5) W24(10.5,-5.5) W25(11.5,-5.5) W26(12.5,-5.5) Y1(-12.5,-6.5) Y2(-11.5,-6.5) Y3(-10.5,-6.5) Y4(-9.5,-6.5) Y23(9.5,-6.5) Y24(10.5,-6.5) Y25(11.5,-6.5) Y26(12.5,-6.5)
Top Overlay:
  circle w0.25: c-14.15,12.5 r0.125
  region: -12.5,13.5 -13.5,12.5 -13.5,13.5
  lines w0.2: -13.5,12.5 -12.5,13.5 ; -13.5,-13.5 -13.5,13.5 13.5,13.5 13.5,-13.5 -13.5,-13.5
Mechanical 13:
  lines w0.1: -13.5,-13.5 -13.5,13.5 13.5,13.5 13.5,-13.5 -13.5,-13.5
Mechanical 15:
  lines w0.1: -0.5,0 0.5,0 ; 0,-0.5 0,0.5 ; -14.5,-14.5 -14.5,14.5 14.5,14.5 14.5,-14.5 -14.5,-14.5
3D body: height 0, standoff 0, extent -13.5,-13.5 13.5,13.5

## BGA100P26X26-456A [mm] "BGA, 456-Leads, Body 27x27mm, Pitch 1mm"
height 2.65
pads (456):
  round 0.5 smd: A1(-12.5,12.5) A2(-11.5,12.5) A3(-10.5,12.5) A4(-9.5,12.5) A5(-8.5,12.5) A6(-7.5,12.5) A7(-6.5,12.5) A8(-5.5,12.5) A9(-4.5,12.5) A10(-3.5,12.5) A11(-2.5,12.5) A12(-1.5,12.5) A13(-0.5,12.5) A14(0.5,12.5) A15(1.5,12.5) A16(2.5,12.5) A17(3.5,12.5) A18(4.5,12.5) A19(5.5,12.5) A20(6.5,12.5) A21(7.5,12.5) A22(8.5,12.5) A23(9.5,12.5) A24(10.5,12.5) A25(11.5,12.5) A26(12.5,12.5) AA1(-12.5,-7.5) AA2(-11.5,-7.5) AA3(-10.5,-7.5) AA4(-9.5,-7.5) AA5(-8.5,-7.5) AA22(8.5,-7.5) AA23(9.5,-7.5) AA24(10.5,-7.5) AA25(11.5,-7.5) AA26(12.5,-7.5) AB1(-12.5,-8.5) AB2(-11.5,-8.5) AB3(-10.5,-8.5) AB4(-9.5,-8.5) AB5(-8.5,-8.5) AB6(-7.5,-8.5) AB7(-6.5,-8.5) AB8(-5.5,-8.5) AB9(-4.5,-8.5) AB10(-3.5,-8.5) AB11(-2.5,-8.5) AB12(-1.5,-8.5) AB13(-0.5,-8.5) AB14(0.5,-8.5) AB15(1.5,-8.5) AB16(2.5,-8.5) AB17(3.5,-8.5) AB18(4.5,-8.5) AB19(5.5,-8.5) AB20(6.5,-8.5) AB21(7.5,-8.5) AB22(8.5,-8.5) AB23(9.5,-8.5) AB24(10.5,-8.5) AB25(11.5,-8.5) AB26(12.5,-8.5) AC1(-12.5,-9.5) AC2(-11.5,-9.5) AC3(-10.5,-9.5) AC4(-9.5,-9.5) AC5(-8.5,-9.5) AC6(-7.5,-9.5) AC7(-6.5,-9.5) AC8(-5.5,-9.5) AC9(-4.5,-9.5) AC10(-3.5,-9.5) AC11(-2.5,-9.5) AC12(-1.5,-9.5) AC13(-0.5,-9.5) AC14(0.5,-9.5) AC15(1.5,-9.5) AC16(2.5,-9.5) AC17(3.5,-9.5) AC18(4.5,-9.5) AC19(5.5,-9.5) AC20(6.5,-9.5) AC21(7.5,-9.5) AC22(8.5,-9.5) AC23(9.5,-9.5) AC24(10.5,-9.5) AC25(11.5,-9.5) AC26(12.5,-9.5) AD1(-12.5,-10.5) AD2(-11.5,-10.5) AD3(-10.5,-10.5) AD4(-9.5,-10.5) AD5(-8.5,-10.5) AD6(-7.5,-10.5) AD7(-6.5,-10.5) AD8(-5.5,-10.5) AD9(-4.5,-10.5) AD10(-3.5,-10.5) AD11(-2.5,-10.5) AD12(-1.5,-10.5) AD13(-0.5,-10.5) AD14(0.5,-10.5) AD15(1.5,-10.5) AD16(2.5,-10.5) AD17(3.5,-10.5) AD18(4.5,-10.5) AD19(5.5,-10.5) AD20(6.5,-10.5) AD21(7.5,-10.5) AD22(8.5,-10.5) AD23(9.5,-10.5) AD24(10.5,-10.5) AD25(11.5,-10.5) AD26(12.5,-10.5) AE1(-12.5,-11.5) AE2(-11.5,-11.5) AE3(-10.5,-11.5) AE4(-9.5,-11.5) AE5(-8.5,-11.5) AE6(-7.5,-11.5) AE7(-6.5,-11.5) AE8(-5.5,-11.5) AE9(-4.5,-11.5) AE10(-3.5,-11.5) AE11(-2.5,-11.5) AE12(-1.5,-11.5) AE13(-0.5,-11.5) AE14(0.5,-11.5) AE15(1.5,-11.5) AE16(2.5,-11.5) AE17(3.5,-11.5) AE18(4.5,-11.5) AE19(5.5,-11.5) AE20(6.5,-11.5) AE21(7.5,-11.5) AE22(8.5,-11.5) AE23(9.5,-11.5) AE24(10.5,-11.5) AE25(11.5,-11.5) AE26(12.5,-11.5) AF1(-12.5,-12.5) AF2(-11.5,-12.5) AF3(-10.5,-12.5) AF4(-9.5,-12.5) AF5(-8.5,-12.5) AF6(-7.5,-12.5) AF7(-6.5,-12.5) AF8(-5.5,-12.5) AF9(-4.5,-12.5) AF10(-3.5,-12.5) AF11(-2.5,-12.5) AF12(-1.5,-12.5) AF13(-0.5,-12.5) AF14(0.5,-12.5) AF15(1.5,-12.5) AF16(2.5,-12.5) AF17(3.5,-12.5) AF18(4.5,-12.5) AF19(5.5,-12.5) AF20(6.5,-12.5) AF21(7.5,-12.5) AF22(8.5,-12.5) AF23(9.5,-12.5) AF24(10.5,-12.5) AF25(11.5,-12.5) AF26(12.5,-12.5) B1(-12.5,11.5) B2(-11.5,11.5) B3(-10.5,11.5) B4(-9.5,11.5) B5(-8.5,11.5) B6(-7.5,11.5) B7(-6.5,11.5) B8(-5.5,11.5) B9(-4.5,11.5) B10(-3.5,11.5) B11(-2.5,11.5) B12(-1.5,11.5) B13(-0.5,11.5) B14(0.5,11.5) B15(1.5,11.5) B16(2.5,11.5) B17(3.5,11.5) B18(4.5,11.5) B19(5.5,11.5) B20(6.5,11.5) B21(7.5,11.5) B22(8.5,11.5) B23(9.5,11.5) B24(10.5,11.5) B25(11.5,11.5) B26(12.5,11.5) C1(-12.5,10.5) C2(-11.5,10.5) C3(-10.5,10.5) C4(-9.5,10.5) C5(-8.5,10.5) C6(-7.5,10.5) C7(-6.5,10.5) C8(-5.5,10.5) C9(-4.5,10.5) C10(-3.5,10.5) C11(-2.5,10.5) C12(-1.5,10.5) C13(-0.5,10.5) C14(0.5,10.5) C15(1.5,10.5) C16(2.5,10.5) C17(3.5,10.5) C18(4.5,10.5) C19(5.5,10.5) C20(6.5,10.5) C21(7.5,10.5) C22(8.5,10.5) C23(9.5,10.5) C24(10.5,10.5) C25(11.5,10.5) C26(12.5,10.5) D1(-12.5,9.5) D2(-11.5,9.5) D3(-10.5,9.5) D4(-9.5,9.5) D5(-8.5,9.5) D6(-7.5,9.5) D7(-6.5,9.5) D8(-5.5,9.5) D9(-4.5,9.5) D10(-3.5,9.5) D11(-2.5,9.5) D12(-1.5,9.5) D13(-0.5,9.5) D14(0.5,9.5) D15(1.5,9.5) D16(2.5,9.5) D17(3.5,9.5) D18(4.5,9.5) D19(5.5,9.5) D20(6.5,9.5) D21(7.5,9.5) D22(8.5,9.5) D23(9.5,9.5) D24(10.5,9.5) D25(11.5,9.5) D26(12.5,9.5) E1(-12.5,8.5) E2(-11.5,8.5) E3(-10.5,8.5) E4(-9.5,8.5) E5(-8.5,8.5) E6(-7.5,8.5) E7(-6.5,8.5) E8(-5.5,8.5) E9(-4.5,8.5) E10(-3.5,8.5) E11(-2.5,8.5) E12(-1.5,8.5) E13(-0.5,8.5) E14(0.5,8.5) E15(1.5,8.5) E16(2.5,8.5) E17(3.5,8.5) E18(4.5,8.5) E19(5.5,8.5) E20(6.5,8.5) E21(7.5,8.5) E22(8.5,8.5) E23(9.5,8.5) E24(10.5,8.5) E25(11.5,8.5) E26(12.5,8.5) F1(-12.5,7.5) F2(-11.5,7.5) F3(-10.5,7.5) F4(-9.5,7.5) F5(-8.5,7.5) F22(8.5,7.5) F23(9.5,7.5) F24(10.5,7.5) F25(11.5,7.5) F26(12.5,7.5) G1(-12.5,6.5) G2(-11.5,6.5) G3(-10.5,6.5) G4(-9.5,6.5) G5(-8.5,6.5) G22(8.5,6.5) G23(9.5,6.5) G24(10.5,6.5) G25(11.5,6.5) G26(12.5,6.5) H1(-12.5,5.5) H2(-11.5,5.5) H3(-10.5,5.5) H4(-9.5,5.5) H5(-8.5,5.5) H22(8.5,5.5) H23(9.5,5.5) H24(10.5,5.5) H25(11.5,5.5) H26(12.5,5.5) J1(-12.5,4.5) J2(-11.5,4.5) J3(-10.5,4.5) J4(-9.5,4.5) J5(-8.5,4.5) J22(8.5,4.5) J23(9.5,4.5) J24(10.5,4.5) J25(11.5,4.5) J26(12.5,4.5) K1(-12.5,3.5) K2(-11.5,3.5) K3(-10.5,3.5) K4(-9.5,3.5) K5(-8.5,3.5) K22(8.5,3.5) K23(9.5,3.5) K24(10.5,3.5) K25(11.5,3.5) K26(12.5,3.5) L1(-12.5,2.5) L2(-11.5,2.5) L3(-10.5,2.5) L4(-9.5,2.5) L5(-8.5,2.5) L11(-2.5,2.5) L12(-1.5,2.5) L13(-0.5,2.5) L14(0.5,2.5) L15(1.5,2.5) L16(2.5,2.5) L22(8.5,2.5) L23(9.5,2.5) L24(10.5,2.5) L25(11.5,2.5) L26(12.5,2.5) M1(-12.5,1.5) M2(-11.5,1.5) M3(-10.5,1.5) M4(-9.5,1.5) M5(-8.5,1.5) M11(-2.5,1.5) M12(-1.5,1.5) M13(-0.5,1.5) M14(0.5,1.5) M15(1.5,1.5) M16(2.5,1.5) M22(8.5,1.5) M23(9.5,1.5) M24(10.5,1.5) M25(11.5,1.5) M26(12.5,1.5) N1(-12.5,0.5) N2(-11.5,0.5) N3(-10.5,0.5) N4(-9.5,0.5) N5(-8.5,0.5) N11(-2.5,0.5) N12(-1.5,0.5) N13(-0.5,0.5) N14(0.5,0.5) N15(1.5,0.5) N16(2.5,0.5) N22(8.5,0.5) N23(9.5,0.5) N24(10.5,0.5) N25(11.5,0.5) N26(12.5,0.5) P1(-12.5,-0.5) P2(-11.5,-0.5) P3(-10.5,-0.5) P4(-9.5,-0.5) P5(-8.5,-0.5) P11(-2.5,-0.5) P12(-1.5,-0.5) P13(-0.5,-0.5) P14(0.5,-0.5) P15(1.5,-0.5) P16(2.5,-0.5) P22(8.5,-0.5) P23(9.5,-0.5) P24(10.5,-0.5) P25(11.5,-0.5) P26(12.5,-0.5) R1(-12.5,-1.5) R2(-11.5,-1.5) R3(-10.5,-1.5) R4(-9.5,-1.5) R5(-8.5,-1.5) R11(-2.5,-1.5) R12(-1.5,-1.5) R13(-0.5,-1.5) R14(0.5,-1.5) R15(1.5,-1.5) R16(2.5,-1.5) R22(8.5,-1.5) R23(9.5,-1.5) R24(10.5,-1.5) R25(11.5,-1.5) R26(12.5,-1.5) T1(-12.5,-2.5) T2(-11.5,-2.5) T3(-10.5,-2.5) T4(-9.5,-2.5) T5(-8.5,-2.5) T11(-2.5,-2.5) T12(-1.5,-2.5) T13(-0.5,-2.5) T14(0.5,-2.5) T15(1.5,-2.5) T16(2.5,-2.5) T22(8.5,-2.5) T23(9.5,-2.5) T24(10.5,-2.5) T25(11.5,-2.5) T26(12.5,-2.5) U1(-12.5,-3.5) U2(-11.5,-3.5) U3(-10.5,-3.5) U4(-9.5,-3.5) U5(-8.5,-3.5) U22(8.5,-3.5) U23(9.5,-3.5) U24(10.5,-3.5) U25(11.5,-3.5) U26(12.5,-3.5) V1(-12.5,-4.5) V2(-11.5,-4.5) V3(-10.5,-4.5) V4(-9.5,-4.5) V5(-8.5,-4.5) V22(8.5,-4.5) V23(9.5,-4.5) V24(10.5,-4.5) V25(11.5,-4.5) V26(12.5,-4.5) W1(-12.5,-5.5) W2(-11.5,-5.5) W3(-10.5,-5.5) W4(-9.5,-5.5) W5(-8.5,-5.5) W22(8.5,-5.5) W23(9.5,-5.5) W24(10.5,-5.5) W25(11.5,-5.5) W26(12.5,-5.5) Y1(-12.5,-6.5) Y2(-11.5,-6.5) Y3(-10.5,-6.5) Y4(-9.5,-6.5) Y5(-8.5,-6.5) Y22(8.5,-6.5) Y23(9.5,-6.5) Y24(10.5,-6.5) Y25(11.5,-6.5) Y26(12.5,-6.5)
Top Overlay:
  circle w0.25: c-14.15,12.5 r0.125
  region: -12.5,13.5 -13.5,12.5 -13.5,13.5
  lines w0.2: -13.5,12.5 -12.5,13.5 ; -13.5,-13.5 -13.5,13.5 13.5,13.5 13.5,-13.5 -13.5,-13.5
Mechanical 13:
  lines w0.1: -13.5,-13.5 -13.5,13.5 13.5,13.5 13.5,-13.5 -13.5,-13.5
Mechanical 15:
  lines w0.1: -0.5,0 0.5,0 ; 0,-0.5 0,0.5 ; -14.5,-14.5 -14.5,14.5 14.5,14.5 14.5,-14.5 -14.5,-14.5
3D body: height 0, standoff 0, extent -13.5,-13.5 13.5,13.5

## BGA100P26X26-484 [mm] "BGA, 484-Leads, Body 27x27mm, Pitch 1mm"
height 2.44
pads (484):
  round 0.5 smd: A1(-12.5,12.5) A2(-11.5,12.5) A3(-10.5,12.5) A4(-9.5,12.5) A5(-8.5,12.5) A6(-7.5,12.5) A7(-6.5,12.5) A8(-5.5,12.5) A9(-4.5,12.5) A10(-3.5,12.5) A11(-2.5,12.5) A12(-1.5,12.5) A13(-0.5,12.5) A14(0.5,12.5) A15(1.5,12.5) A16(2.5,12.5) A17(3.5,12.5) A18(4.5,12.5) A19(5.5,12.5) A20(6.5,12.5) A21(7.5,12.5) A22(8.5,12.5) A23(9.5,12.5) A24(10.5,12.5) A25(11.5,12.5) A26(12.5,12.5) AA1(-12.5,-7.5) AA2(-11.5,-7.5) AA3(-10.5,-7.5) AA4(-9.5,-7.5) AA5(-8.5,-7.5) AA22(8.5,-7.5) AA23(9.5,-7.5) AA24(10.5,-7.5) AA25(11.5,-7.5) AA26(12.5,-7.5) AB1(-12.5,-8.5) AB2(-11.5,-8.5) AB3(-10.5,-8.5) AB4(-9.5,-8.5) AB5(-8.5,-8.5) AB6(-7.5,-8.5) AB7(-6.5,-8.5) AB8(-5.5,-8.5) AB9(-4.5,-8.5) AB10(-3.5,-8.5) AB11(-2.5,-8.5) AB12(-1.5,-8.5) AB13(-0.5,-8.5) AB14(0.5,-8.5) AB15(1.5,-8.5) AB16(2.5,-8.5) AB17(3.5,-8.5) AB18(4.5,-8.5) AB19(5.5,-8.5) AB20(6.5,-8.5) AB21(7.5,-8.5) AB22(8.5,-8.5) AB23(9.5,-8.5) AB24(10.5,-8.5) AB25(11.5,-8.5) AB26(12.5,-8.5) AC1(-12.5,-9.5) AC2(-11.5,-9.5) AC3(-10.5,-9.5) AC4(-9.5,-9.5) AC5(-8.5,-9.5) AC6(-7.5,-9.5) AC7(-6.5,-9.5) AC8(-5.5,-9.5) AC9(-4.5,-9.5) AC10(-3.5,-9.5) AC11(-2.5,-9.5) AC12(-1.5,-9.5) AC13(-0.5,-9.5) AC14(0.5,-9.5) AC15(1.5,-9.5) AC16(2.5,-9.5) AC17(3.5,-9.5) AC18(4.5,-9.5) AC19(5.5,-9.5) AC20(6.5,-9.5) AC21(7.5,-9.5) AC22(8.5,-9.5) AC23(9.5,-9.5) AC24(10.5,-9.5) AC25(11.5,-9.5) AC26(12.5,-9.5) AD1(-12.5,-10.5) AD2(-11.5,-10.5) AD3(-10.5,-10.5) AD4(-9.5,-10.5) AD5(-8.5,-10.5) AD6(-7.5,-10.5) AD7(-6.5,-10.5) AD8(-5.5,-10.5) AD9(-4.5,-10.5) AD10(-3.5,-10.5) AD11(-2.5,-10.5) AD12(-1.5,-10.5) AD13(-0.5,-10.5) AD14(0.5,-10.5) AD15(1.5,-10.5) AD16(2.5,-10.5) AD17(3.5,-10.5) AD18(4.5,-10.5) AD19(5.5,-10.5) AD20(6.5,-10.5) AD21(7.5,-10.5) AD22(8.5,-10.5) AD23(9.5,-10.5) AD24(10.5,-10.5) AD25(11.5,-10.5) AD26(12.5,-10.5) AE1(-12.5,-11.5) AE2(-11.5,-11.5) AE3(-10.5,-11.5) AE4(-9.5,-11.5) AE5(-8.5,-11.5) AE6(-7.5,-11.5) AE7(-6.5,-11.5) AE8(-5.5,-11.5) AE9(-4.5,-11.5) AE10(-3.5,-11.5) AE11(-2.5,-11.5) AE12(-1.5,-11.5) AE13(-0.5,-11.5) AE14(0.5,-11.5) AE15(1.5,-11.5) AE16(2.5,-11.5) AE17(3.5,-11.5) AE18(4.5,-11.5) AE19(5.5,-11.5) AE20(6.5,-11.5) AE21(7.5,-11.5) AE22(8.5,-11.5) AE23(9.5,-11.5) AE24(10.5,-11.5) AE25(11.5,-11.5) AE26(12.5,-11.5) AF1(-12.5,-12.5) AF2(-11.5,-12.5) AF3(-10.5,-12.5) AF4(-9.5,-12.5) AF5(-8.5,-12.5) AF6(-7.5,-12.5) AF7(-6.5,-12.5) AF8(-5.5,-12.5) AF9(-4.5,-12.5) AF10(-3.5,-12.5) AF11(-2.5,-12.5) AF12(-1.5,-12.5) AF13(-0.5,-12.5) AF14(0.5,-12.5) AF15(1.5,-12.5) AF16(2.5,-12.5) AF17(3.5,-12.5) AF18(4.5,-12.5) AF19(5.5,-12.5) AF20(6.5,-12.5) AF21(7.5,-12.5) AF22(8.5,-12.5) AF23(9.5,-12.5) AF24(10.5,-12.5) AF25(11.5,-12.5) AF26(12.5,-12.5) B1(-12.5,11.5) B2(-11.5,11.5) B3(-10.5,11.5) B4(-9.5,11.5) B5(-8.5,11.5) B6(-7.5,11.5) B7(-6.5,11.5) B8(-5.5,11.5) B9(-4.5,11.5) B10(-3.5,11.5) B11(-2.5,11.5) B12(-1.5,11.5) B13(-0.5,11.5) B14(0.5,11.5) B15(1.5,11.5) B16(2.5,11.5) B17(3.5,11.5) B18(4.5,11.5) B19(5.5,11.5) B20(6.5,11.5) B21(7.5,11.5) B22(8.5,11.5) B23(9.5,11.5) B24(10.5,11.5) B25(11.5,11.5) B26(12.5,11.5) C1(-12.5,10.5) C2(-11.5,10.5) C3(-10.5,10.5) C4(-9.5,10.5) C5(-8.5,10.5) C6(-7.5,10.5) C7(-6.5,10.5) C8(-5.5,10.5) C9(-4.5,10.5) C10(-3.5,10.5) C11(-2.5,10.5) C12(-1.5,10.5) C13(-0.5,10.5) C14(0.5,10.5) C15(1.5,10.5) C16(2.5,10.5) C17(3.5,10.5) C18(4.5,10.5) C19(5.5,10.5) C20(6.5,10.5) C21(7.5,10.5) C22(8.5,10.5) C23(9.5,10.5) C24(10.5,10.5) C25(11.5,10.5) C26(12.5,10.5) D1(-12.5,9.5) D2(-11.5,9.5) D3(-10.5,9.5) D4(-9.5,9.5) D5(-8.5,9.5) D6(-7.5,9.5) D7(-6.5,9.5) D8(-5.5,9.5) D9(-4.5,9.5) D10(-3.5,9.5) D11(-2.5,9.5) D12(-1.5,9.5) D13(-0.5,9.5) D14(0.5,9.5) D15(1.5,9.5) D16(2.5,9.5) D17(3.5,9.5) D18(4.5,9.5) D19(5.5,9.5) D20(6.5,9.5) D21(7.5,9.5) D22(8.5,9.5) D23(9.5,9.5) D24(10.5,9.5) D25(11.5,9.5) D26(12.5,9.5) E1(-12.5,8.5) E2(-11.5,8.5) E3(-10.5,8.5) E4(-9.5,8.5) E5(-8.5,8.5) E6(-7.5,8.5) E7(-6.5,8.5) E8(-5.5,8.5) E9(-4.5,8.5) E10(-3.5,8.5) E11(-2.5,8.5) E12(-1.5,8.5) E13(-0.5,8.5) E14(0.5,8.5) E15(1.5,8.5) E16(2.5,8.5) E17(3.5,8.5) E18(4.5,8.5) E19(5.5,8.5) E20(6.5,8.5) E21(7.5,8.5) E22(8.5,8.5) E23(9.5,8.5) E24(10.5,8.5) E25(11.5,8.5) E26(12.5,8.5) F1(-12.5,7.5) F2(-11.5,7.5) F3(-10.5,7.5) F4(-9.5,7.5) F5(-8.5,7.5) F22(8.5,7.5) F23(9.5,7.5) F24(10.5,7.5) F25(11.5,7.5) F26(12.5,7.5) G1(-12.5,6.5) G2(-11.5,6.5) G3(-10.5,6.5) G4(-9.5,6.5) G5(-8.5,6.5) G22(8.5,6.5) G23(9.5,6.5) G24(10.5,6.5) G25(11.5,6.5) G26(12.5,6.5) H1(-12.5,5.5) H2(-11.5,5.5) H3(-10.5,5.5) H4(-9.5,5.5) H5(-8.5,5.5) H22(8.5,5.5) H23(9.5,5.5) H24(10.5,5.5) H25(11.5,5.5) H26(12.5,5.5) J1(-12.5,4.5) J2(-11.5,4.5) J3(-10.5,4.5) J4(-9.5,4.5) J5(-8.5,4.5) J22(8.5,4.5) J23(9.5,4.5) J24(10.5,4.5) J25(11.5,4.5) J26(12.5,4.5) K1(-12.5,3.5) K2(-11.5,3.5) K3(-10.5,3.5) K4(-9.5,3.5) K5(-8.5,3.5) K10(-3.5,3.5) K11(-2.5,3.5) K12(-1.5,3.5) K13(-0.5,3.5) K14(0.5,3.5) K15(1.5,3.5) K16(2.5,3.5) K17(3.5,3.5) K22(8.5,3.5) K23(9.5,3.5) K24(10.5,3.5) K25(11.5,3.5) K26(12.5,3.5) L1(-12.5,2.5) L2(-11.5,2.5) L3(-10.5,2.5) L4(-9.5,2.5) L5(-8.5,2.5) L10(-3.5,2.5) L11(-2.5,2.5) L12(-1.5,2.5) L13(-0.5,2.5) L14(0.5,2.5) L15(1.5,2.5) L16(2.5,2.5) L17(3.5,2.5) L22(8.5,2.5) L23(9.5,2.5) L24(10.5,2.5) L25(11.5,2.5) L26(12.5,2.5) M1(-12.5,1.5) M2(-11.5,1.5) M3(-10.5,1.5) M4(-9.5,1.5) M5(-8.5,1.5) M10(-3.5,1.5) M11(-2.5,1.5) M12(-1.5,1.5) M13(-0.5,1.5) M14(0.5,1.5) M15(1.5,1.5) M16(2.5,1.5) M17(3.5,1.5) M22(8.5,1.5) M23(9.5,1.5) M24(10.5,1.5) M25(11.5,1.5) M26(12.5,1.5) N1(-12.5,0.5) N2(-11.5,0.5) N3(-10.5,0.5) N4(-9.5,0.5) N5(-8.5,0.5) N10(-3.5,0.5) N11(-2.5,0.5) N12(-1.5,0.5) N13(-0.5,0.5) N14(0.5,0.5) N15(1.5,0.5) N16(2.5,0.5) N17(3.5,0.5) N22(8.5,0.5) N23(9.5,0.5) N24(10.5,0.5) N25(11.5,0.5) N26(12.5,0.5) P1(-12.5,-0.5) P2(-11.5,-0.5) P3(-10.5,-0.5) P4(-9.5,-0.5) P5(-8.5,-0.5) P10(-3.5,-0.5) P11(-2.5,-0.5) P12(-1.5,-0.5) P13(-0.5,-0.5) P14(0.5,-0.5) P15(1.5,-0.5) P16(2.5,-0.5) P17(3.5,-0.5) P22(8.5,-0.5) P23(9.5,-0.5) P24(10.5,-0.5) P25(11.5,-0.5) P26(12.5,-0.5) R1(-12.5,-1.5) R2(-11.5,-1.5) R3(-10.5,-1.5) R4(-9.5,-1.5) R5(-8.5,-1.5) R10(-3.5,-1.5) R11(-2.5,-1.5) R12(-1.5,-1.5) R13(-0.5,-1.5) R14(0.5,-1.5) R15(1.5,-1.5) R16(2.5,-1.5) R17(3.5,-1.5) R22(8.5,-1.5) R23(9.5,-1.5) R24(10.5,-1.5) R25(11.5,-1.5) R26(12.5,-1.5) T1(-12.5,-2.5) T2(-11.5,-2.5) T3(-10.5,-2.5) T4(-9.5,-2.5) T5(-8.5,-2.5) T10(-3.5,-2.5) T11(-2.5,-2.5) T12(-1.5,-2.5) T13(-0.5,-2.5) T14(0.5,-2.5) T15(1.5,-2.5) T16(2.5,-2.5) T17(3.5,-2.5) T22(8.5,-2.5) T23(9.5,-2.5) T24(10.5,-2.5) T25(11.5,-2.5) T26(12.5,-2.5) U1(-12.5,-3.5) U2(-11.5,-3.5) U3(-10.5,-3.5) U4(-9.5,-3.5) U5(-8.5,-3.5) U10(-3.5,-3.5) U11(-2.5,-3.5) U12(-1.5,-3.5) U13(-0.5,-3.5) U14(0.5,-3.5) U15(1.5,-3.5) U16(2.5,-3.5) U17(3.5,-3.5) U22(8.5,-3.5) U23(9.5,-3.5) U24(10.5,-3.5) U25(11.5,-3.5) U26(12.5,-3.5) V1(-12.5,-4.5) V2(-11.5,-4.5) V3(-10.5,-4.5) V4(-9.5,-4.5) V5(-8.5,-4.5) V22(8.5,-4.5) V23(9.5,-4.5) V24(10.5,-4.5) V25(11.5,-4.5) V26(12.5,-4.5) W1(-12.5,-5.5) W2(-11.5,-5.5) W3(-10.5,-5.5) W4(-9.5,-5.5) W5(-8.5,-5.5) W22(8.5,-5.5) W23(9.5,-5.5) W24(10.5,-5.5) W25(11.5,-5.5) W26(12.5,-5.5) Y1(-12.5,-6.5) Y2(-11.5,-6.5) Y3(-10.5,-6.5) Y4(-9.5,-6.5) Y5(-8.5,-6.5) Y22(8.5,-6.5) Y23(9.5,-6.5) Y24(10.5,-6.5) Y25(11.5,-6.5) Y26(12.5,-6.5)
Top Overlay:
  circle w0.25: c-14.15,12.5 r0.125
  region: -12.5,13.5 -13.5,12.5 -13.5,13.5
  lines w0.2: -13.5,12.5 -12.5,13.5 ; -13.5,-13.5 -13.5,13.5 13.5,13.5 13.5,-13.5 -13.5,-13.5
Mechanical 13:
  lines w0.1: -13.5,-13.5 -13.5,13.5 13.5,13.5 13.5,-13.5 -13.5,-13.5
Mechanical 15:
  lines w0.1: -0.5,0 0.5,0 ; 0,-0.5 0,0.5 ; -14.5,-14.5 -14.5,14.5 14.5,14.5 14.5,-14.5 -14.5,-14.5
3D body: height 0, standoff 0, extent -13.5,-13.5 13.5,13.5

## BGA100P26X26-665 [mm] "665-Ball Flip Chip Fine Pitch Ball Grid Array (FF665)"
height 3
pads (665):
  round 0.5 smd: A2(-11.5,12.5) A3(-10.5,12.5) A4(-9.5,12.5) A5(-8.5,12.5) A6(-7.5,12.5) A7(-6.5,12.5) A8(-5.5,12.5) A9(-4.5,12.5) A10(-3.5,12.5) A11(-2.5,12.5) A12(-1.5,12.5) A13(-0.5,12.5) A14(0.5,12.5) A15(1.5,12.5) A16(2.5,12.5) A17(3.5,12.5) A18(4.5,12.5) A19(5.5,12.5) A20(6.5,12.5) A21(7.5,12.5) A22(8.5,12.5) A23(9.5,12.5) A24(10.5,12.5) A25(11.5,12.5) A26(12.5,12.5) AA1(-12.5,-7.5) AA2(-11.5,-7.5) AA3(-10.5,-7.5) AA4(-9.5,-7.5) AA5(-8.5,-7.5) AA6(-7.5,-7.5) AA7(-6.5,-7.5) AA8(-5.5,-7.5) AA9(-4.5,-7.5) AA10(-3.5,-7.5) AA11(-2.5,-7.5) AA12(-1.5,-7.5) AA13(-0.5,-7.5) AA14(0.5,-7.5) AA15(1.5,-7.5) AA16(2.5,-7.5) AA17(3.5,-7.5) AA18(4.5,-7.5) AA19(5.5,-7.5) AA20(6.5,-7.5) AA21(7.5,-7.5) AA22(8.5,-7.5) AA23(9.5,-7.5) AA24(10.5,-7.5) AA25(11.5,-7.5) AA26(12.5,-7.5) AB1(-12.5,-8.5) AB2(-11.5,-8.5) AB3(-10.5,-8.5) AB4(-9.5,-8.5) AB5(-8.5,-8.5) AB6(-7.5,-8.5) AB7(-6.5,-8.5) AB8(-5.5,-8.5) AB9(-4.5,-8.5) AB10(-3.5,-8.5) AB11(-2.5,-8.5) AB12(-1.5,-8.5) AB13(-0.5,-8.5) AB14(0.5,-8.5) AB15(1.5,-8.5) AB16(2.5,-8.5) AB17(3.5,-8.5) AB18(4.5,-8.5) AB19(5.5,-8.5) AB20(6.5,-8.5) AB21(7.5,-8.5) AB22(8.5,-8.5) AB23(9.5,-8.5) AB24(10.5,-8.5) AB25(11.5,-8.5) AB26(12.5,-8.5) AC1(-12.5,-9.5) AC2(-11.5,-9.5) AC3(-10.5,-9.5) AC4(-9.5,-9.5) AC5(-8.5,-9.5) AC6(-7.5,-9.5) AC7(-6.5,-9.5) AC8(-5.5,-9.5) AC9(-4.5,-9.5) AC10(-3.5,-9.5) AC11(-2.5,-9.5) AC12(-1.5,-9.5) AC13(-0.5,-9.5) AC14(0.5,-9.5) AC15(1.5,-9.5) AC16(2.5,-9.5) AC17(3.5,-9.5) AC18(4.5,-9.5) AC19(5.5,-9.5) AC20(6.5,-9.5) AC21(7.5,-9.5) AC22(8.5,-9.5) AC23(9.5,-9.5) AC24(10.5,-9.5) AC25(11.5,-9.5) AC26(12.5,-9.5) AD1(-12.5,-10.5) AD2(-11.5,-10.5) AD3(-10.5,-10.5) AD4(-9.5,-10.5) AD5(-8.5,-10.5) AD6(-7.5,-10.5) AD7(-6.5,-10.5) AD8(-5.5,-10.5) AD9(-4.5,-10.5) AD10(-3.5,-10.5) AD11(-2.5,-10.5) AD12(-1.5,-10.5) AD13(-0.5,-10.5) AD14(0.5,-10.5) AD15(1.5,-10.5) AD16(2.5,-10.5) AD17(3.5,-10.5) AD18(4.5,-10.5) AD19(5.5,-10.5) AD20(6.5,-10.5) AD21(7.5,-10.5) AD22(8.5,-10.5) AD23(9.5,-10.5) AD24(10.5,-10.5) AD25(11.5,-10.5) AD26(12.5,-10.5) AE2(-11.5,-11.5) AE3(-10.5,-11.5) AE4(-9.5,-11.5) AE5(-8.5,-11.5) AE6(-7.5,-11.5) AE7(-6.5,-11.5) AE8(-5.5,-11.5) AE9(-4.5,-11.5) AE10(-3.5,-11.5) AE11(-2.5,-11.5) AE12(-1.5,-11.5) AE13(-0.5,-11.5) AE14(0.5,-11.5) AE15(1.5,-11.5) AE16(2.5,-11.5) AE17(3.5,-11.5) AE18(4.5,-11.5) AE19(5.5,-11.5) AE20(6.5,-11.5) AE21(7.5,-11.5) AE22(8.5,-11.5) AE23(9.5,-11.5) AE24(10.5,-11.5) AE25(11.5,-11.5) AE26(12.5,-11.5) AF2(-11.5,-12.5) AF3(-10.5,-12.5) AF4(-9.5,-12.5) AF5(-8.5,-12.5) AF6(-7.5,-12.5) AF7(-6.5,-12.5) AF8(-5.5,-12.5) AF9(-4.5,-12.5) AF10(-3.5,-12.5) AF11(-2.5,-12.5) AF12(-1.5,-12.5) AF13(-0.5,-12.5) AF14(0.5,-12.5) AF15(1.5,-12.5) AF16(2.5,-12.5) AF17(3.5,-12.5) AF18(4.5,-12.5) AF19(5.5,-12.5) AF20(6.5,-12.5) AF21(7.5,-12.5) AF22(8.5,-12.5) AF23(9.5,-12.5) AF24(10.5,-12.5) AF25(11.5,-12.5) AF26(12.5,-12.5) B2(-11.5,11.5) B3(-10.5,11.5) B4(-9.5,11.5) B5(-8.5,11.5) B6(-7.5,11.5) B7(-6.5,11.5) B8(-5.5,11.5) B9(-4.5,11.5) B10(-3.5,11.5) B11(-2.5,11.5) B12(-1.5,11.5) B13(-0.5,11.5) B14(0.5,11.5) B15(1.5,11.5) B16(2.5,11.5) B17(3.5,11.5) B18(4.5,11.5) B19(5.5,11.5) B20(6.5,11.5) B21(7.5,11.5) B22(8.5,11.5) B23(9.5,11.5) B24(10.5,11.5) B25(11.5,11.5) B26(12.5,11.5) C1(-12.5,10.5) C2(-11.5,10.5) C3(-10.5,10.5) C4(-9.5,10.5) C5(-8.5,10.5) C6(-7.5,10.5) C7(-6.5,10.5) C8(-5.5,10.5) C9(-4.5,10.5) C10(-3.5,10.5) C11(-2.5,10.5) C12(-1.5,10.5) C13(-0.5,10.5) C14(0.5,10.5) C15(1.5,10.5) C16(2.5,10.5) C17(3.5,10.5) C18(4.5,10.5) C19(5.5,10.5) C20(6.5,10.5) C21(7.5,10.5) C22(8.5,10.5) C23(9.5,10.5) C24(10.5,10.5) C25(11.5,10.5) C26(12.5,10.5) D1(-12.5,9.5) D2(-11.5,9.5) D3(-10.5,9.5) D4(-9.5,9.5) D5(-8.5,9.5) D6(-7.5,9.5) D7(-6.5,9.5) D8(-5.5,9.5) D9(-4.5,9.5) D10(-3.5,9.5) D11(-2.5,9.5) D12(-1.5,9.5) D13(-0.5,9.5) D14(0.5,9.5) D15(1.5,9.5) D16(2.5,9.5) D17(3.5,9.5) D18(4.5,9.5) D19(5.5,9.5) D20(6.5,9.5) D21(7.5,9.5) D22(8.5,9.5) D23(9.5,9.5) D24(10.5,9.5) D25(11.5,9.5) D26(12.5,9.5) E1(-12.5,8.5) E2(-11.5,8.5) E3(-10.5,8.5) E4(-9.5,8.5) E5(-8.5,8.5) E6(-7.5,8.5) E7(-6.5,8.5) E8(-5.5,8.5) E9(-4.5,8.5) E10(-3.5,8.5) E11(-2.5,8.5) E12(-1.5,8.5) E13(-0.5,8.5) E14(0.5,8.5) E15(1.5,8.5) E16(2.5,8.5) E17(3.5,8.5) E18(4.5,8.5) E19(5.5,8.5) E20(6.5,8.5) E21(7.5,8.5) E22(8.5,8.5) E23(9.5,8.5) E24(10.5,8.5) E25(11.5,8.5) E26(12.5,8.5) F1(-12.5,7.5) F2(-11.5,7.5) F3(-10.5,7.5) F4(-9.5,7.5) F5(-8.5,7.5) F6(-7.5,7.5) F7(-6.5,7.5) F8(-5.5,7.5) F9(-4.5,7.5) F10(-3.5,7.5) F11(-2.5,7.5) F12(-1.5,7.5) F13(-0.5,7.5) F14(0.5,7.5) F15(1.5,7.5) F16(2.5,7.5) F17(3.5,7.5) F18(4.5,7.5) F19(5.5,7.5) F20(6.5,7.5) F21(7.5,7.5) F22(8.5,7.5) F23(9.5,7.5) F24(10.5,7.5) F25(11.5,7.5) F26(12.5,7.5) G2(-11.5,6.5) G3(-10.5,6.5) G4(-9.5,6.5) G5(-8.5,6.5) G6(-7.5,6.5) G7(-6.5,6.5) G8(-5.5,6.5) G9(-4.5,6.5) G10(-3.5,6.5) G11(-2.5,6.5) G12(-1.5,6.5) G13(-0.5,6.5) G14(0.5,6.5) G15(1.5,6.5) G16(2.5,6.5) G17(3.5,6.5) G18(4.5,6.5) G19(5.5,6.5) G20(6.5,6.5) G21(7.5,6.5) G22(8.5,6.5) G23(9.5,6.5) G24(10.5,6.5) G25(11.5,6.5) G26(12.5,6.5) H2(-11.5,5.5) H3(-10.5,5.5) H4(-9.5,5.5) H5(-8.5,5.5) H6(-7.5,5.5) H7(-6.5,5.5) H8(-5.5,5.5) H9(-4.5,5.5) H10(-3.5,5.5) H11(-2.5,5.5) H12(-1.5,5.5) H13(-0.5,5.5) H14(0.5,5.5) H15(1.5,5.5) H16(2.5,5.5) H17(3.5,5.5) H18(4.5,5.5) H19(5.5,5.5) H20(6.5,5.5) H21(7.5,5.5) H22(8.5,5.5) H23(9.5,5.5) H24(10.5,5.5) H25(11.5,5.5) H26(12.5,5.5) J1(-12.5,4.5) J2(-11.5,4.5) J3(-10.5,4.5) J4(-9.5,4.5) J5(-8.5,4.5) J6(-7.5,4.5) J7(-6.5,4.5) J8(-5.5,4.5) J10(-3.5,4.5) J11(-2.5,4.5) J12(-1.5,4.5) J13(-0.5,4.5) J14(0.5,4.5) J15(1.5,4.5) J16(2.5,4.5) J17(3.5,4.5) J18(4.5,4.5) J19(5.5,4.5) J20(6.5,4.5) J21(7.5,4.5) J22(8.5,4.5) J23(9.5,4.5) J24(10.5,4.5) J25(11.5,4.5) J26(12.5,4.5) K1(-12.5,3.5) K2(-11.5,3.5) K3(-10.5,3.5) K4(-9.5,3.5) K5(-8.5,3.5) K6(-7.5,3.5) K7(-6.5,3.5) K8(-5.5,3.5) K9(-4.5,3.5) K10(-3.5,3.5) K11(-2.5,3.5) K12(-1.5,3.5) K13(-0.5,3.5) K14(0.5,3.5) K15(1.5,3.5) K16(2.5,3.5) K17(3.5,3.5) K18(4.5,3.5) K19(5.5,3.5) K20(6.5,3.5) K21(7.5,3.5) K22(8.5,3.5) K23(9.5,3.5) K24(10.5,3.5) K25(11.5,3.5) K26(12.5,3.5) L1(-12.5,2.5) L2(-11.5,2.5) L3(-10.5,2.5) L4(-9.5,2.5) L5(-8.5,2.5) L6(-7.5,2.5) L7(-6.5,2.5) L8(-5.5,2.5) L9(-4.5,2.5) L10(-3.5,2.5) L11(-2.5,2.5) L12(-1.5,2.5) L13(-0.5,2.5) L14(0.5,2.5) L15(1.5,2.5) L16(2.5,2.5) L17(3.5,2.5) L18(4.5,2.5) L19(5.5,2.5) L20(6.5,2.5) L21(7.5,2.5) L22(8.5,2.5) L23(9.5,2.5) L24(10.5,2.5) L25(11.5,2.5) L26(12.5,2.5) M1(-12.5,1.5) M2(-11.5,1.5) M3(-10.5,1.5) M4(-9.5,1.5) M5(-8.5,1.5) M6(-7.5,1.5) M7(-6.5,1.5) M8(-5.5,1.5) M9(-4.5,1.5) M10(-3.5,1.5) M11(-2.5,1.5) M12(-1.5,1.5) M13(-0.5,1.5) M14(0.5,1.5) M15(1.5,1.5) M16(2.5,1.5) M17(3.5,1.5) M18(4.5,1.5) M19(5.5,1.5) M20(6.5,1.5) M21(7.5,1.5) M22(8.5,1.5) M23(9.5,1.5) M24(10.5,1.5) M25(11.5,1.5) M26(12.5,1.5) N2(-11.5,0.5) N3(-10.5,0.5) N4(-9.5,0.5) N5(-8.5,0.5) N6(-7.5,0.5) N7(-6.5,0.5) N8(-5.5,0.5) N9(-4.5,0.5) N10(-3.5,0.5) N11(-2.5,0.5) N12(-1.5,0.5) N13(-0.5,0.5) N14(0.5,0.5) N15(1.5,0.5) N16(2.5,0.5) N17(3.5,0.5) N18(4.5,0.5) N19(5.5,0.5) N20(6.5,0.5) N21(7.5,0.5) N22(8.5,0.5) N23(9.5,0.5) N24(10.5,0.5) N25(11.5,0.5) N26(12.5,0.5) P2(-11.5,-0.5) P3(-10.5,-0.5) P4(-9.5,-0.5) P5(-8.5,-0.5) P6(-7.5,-0.5) P7(-6.5,-0.5) P8(-5.5,-0.5) P9(-4.5,-0.5) P10(-3.5,-0.5) P11(-2.5,-0.5) P12(-1.5,-0.5) P13(-0.5,-0.5) P14(0.5,-0.5) P15(1.5,-0.5) P16(2.5,-0.5) P17(3.5,-0.5) P18(4.5,-0.5) P19(5.5,-0.5) P20(6.5,-0.5) P21(7.5,-0.5) P22(8.5,-0.5) P23(9.5,-0.5) P24(10.5,-0.5) P25(11.5,-0.5) P26(12.5,-0.5) R1(-12.5,-1.5) R2(-11.5,-1.5) R3(-10.5,-1.5) R4(-9.5,-1.5) R5(-8.5,-1.5) R6(-7.5,-1.5) R7(-6.5,-1.5) R8(-5.5,-1.5) R9(-4.5,-1.5) R10(-3.5,-1.5) R11(-2.5,-1.5) R12(-1.5,-1.5) R13(-0.5,-1.5) R14(0.5,-1.5) R15(1.5,-1.5) R16(2.5,-1.5) R17(3.5,-1.5) R18(4.5,-1.5) R19(5.5,-1.5) R20(6.5,-1.5) R21(7.5,-1.5) R22(8.5,-1.5) R23(9.5,-1.5) R24(10.5,-1.5) R25(11.5,-1.5) R26(12.5,-1.5) T1(-12.5,-2.5) T2(-11.5,-2.5) T3(-10.5,-2.5) T4(-9.5,-2.5) T5(-8.5,-2.5) T6(-7.5,-2.5) T7(-6.5,-2.5) T8(-5.5,-2.5) T9(-4.5,-2.5) T10(-3.5,-2.5) T11(-2.5,-2.5) T12(-1.5,-2.5) T13(-0.5,-2.5) T14(0.5,-2.5) T15(1.5,-2.5) T16(2.5,-2.5) T17(3.5,-2.5) T18(4.5,-2.5) T19(5.5,-2.5) T20(6.5,-2.5) T21(7.5,-2.5) T22(8.5,-2.5) T23(9.5,-2.5) T24(10.5,-2.5) T25(11.5,-2.5) T26(12.5,-2.5) U1(-12.5,-3.5) U2(-11.5,-3.5) U3(-10.5,-3.5) U4(-9.5,-3.5) U5(-8.5,-3.5) U6(-7.5,-3.5) U7(-6.5,-3.5) U8(-5.5,-3.5) U9(-4.5,-3.5) U10(-3.5,-3.5) U11(-2.5,-3.5) U12(-1.5,-3.5) U13(-0.5,-3.5) U14(0.5,-3.5) U15(1.5,-3.5) U16(2.5,-3.5) U17(3.5,-3.5) U18(4.5,-3.5) U19(5.5,-3.5) U20(6.5,-3.5) U21(7.5,-3.5) U22(8.5,-3.5) U23(9.5,-3.5) U24(10.5,-3.5) U25(11.5,-3.5) U26(12.5,-3.5) V1(-12.5,-4.5) V2(-11.5,-4.5) V3(-10.5,-4.5) V4(-9.5,-4.5) V5(-8.5,-4.5) V6(-7.5,-4.5) V7(-6.5,-4.5) V8(-5.5,-4.5) V9(-4.5,-4.5) V10(-3.5,-4.5) V11(-2.5,-4.5) V12(-1.5,-4.5) V13(-0.5,-4.5) V14(0.5,-4.5) V15(1.5,-4.5) V16(2.5,-4.5) V17(3.5,-4.5) V18(4.5,-4.5) V19(5.5,-4.5) V20(6.5,-4.5) V21(7.5,-4.5) V22(8.5,-4.5) V23(9.5,-4.5) V24(10.5,-4.5) V25(11.5,-4.5) V26(12.5,-4.5) W2(-11.5,-5.5) W3(-10.5,-5.5) W4(-9.5,-5.5) W5(-8.5,-5.5) W6(-7.5,-5.5) W7(-6.5,-5.5) W8(-5.5,-5.5) W9(-4.5,-5.5) W10(-3.5,-5.5) W11(-2.5,-5.5) W12(-1.5,-5.5) W13(-0.5,-5.5) W14(0.5,-5.5) W15(1.5,-5.5) W16(2.5,-5.5) W17(3.5,-5.5) W18(4.5,-5.5) W19(5.5,-5.5) W20(6.5,-5.5) W21(7.5,-5.5) W22(8.5,-5.5) W23(9.5,-5.5) W24(10.5,-5.5) W25(11.5,-5.5) W26(12.5,-5.5) Y2(-11.5,-6.5) Y3(-10.5,-6.5) Y4(-9.5,-6.5) Y5(-8.5,-6.5) Y6(-7.5,-6.5) Y7(-6.5,-6.5) Y8(-5.5,-6.5) Y9(-4.5,-6.5) Y10(-3.5,-6.5) Y11(-2.5,-6.5) Y12(-1.5,-6.5) Y13(-0.5,-6.5) Y14(0.5,-6.5) Y15(1.5,-6.5) Y16(2.5,-6.5) Y17(3.5,-6.5) Y18(4.5,-6.5) Y19(5.5,-6.5) Y20(6.5,-6.5) Y21(7.5,-6.5) Y22(8.5,-6.5) Y23(9.5,-6.5) Y24(10.5,-6.5) Y25(11.5,-6.5) Y26(12.5,-6.5)
Top Overlay:
  circle w0.25: c-14.15,12.5 r0.125
  region: -12.5,13.5 -13.5,12.5 -13.5,13.5
  lines w0.2: -13.5,12.5 -12.5,13.5 ; -13.5,-13.5 13.5,-13.5 13.5,13.5 -13.5,13.5 -13.5,-13.5
Mechanical 13:
  lines w0.1: -13.5,-13.5 13.5,-13.5 13.5,13.5 -13.5,13.5 -13.5,-13.5
Mechanical 15:
  lines w0.1: -0.5,0 0.5,0 ; 0,-0.5 0,0.5 ; -14.5,-14.5 14.5,-14.5 14.5,14.5 -14.5,14.5 -14.5,-14.5
3D body: height 0, standoff 0, extent -13.5,-13.5 13.5,13.5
